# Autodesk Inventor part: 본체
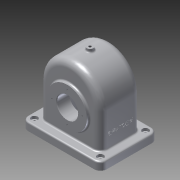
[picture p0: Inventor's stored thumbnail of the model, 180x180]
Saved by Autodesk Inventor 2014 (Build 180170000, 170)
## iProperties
Created: 2016-10
Part Number: 본체
Material: 알루미늄 6061
Document SubType Name: Modeling
Designer: a
Density: 2.71 g/cm^3
Appearance: 알루미늄 - 평지
Mass: 1261.07 g
Surface Area: 1205.98 cm^2
Volume: 465.341 cm^3
Author: a
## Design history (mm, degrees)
sketch "스케치1"
  geometry: L1 (110, 15)-(0, 15); L2 (0, 15)-(0, 0); L3 (0, 0)-(110, 0); L4 (110, 0)-(110, 15)
  constraints: 8 end point, 2 parallel, 1 horizontal, 1 perpendicular
  dimensions: "d0" = 15 distance of L1.end L2.end; "d1" = 110 distance of L1.start L1.end
extrude "돌출1" new body sketch "스케치1" distance "d2" = 150; taper "d3" = 0 deg
node "작업 평면1"
sketch "스케치2"
  geometry: L1 (0, 0)-(-150, 0) reference; L2 (-150, 0)-(-150, 15) reference; L3 (-150, 15)-(0, 15) reference; L4 (0, 15)-(0, 0) reference; L5 (-133, 15)-(-133, 138); L6 (-133, 138)-(-17, 138); L7 (-17, 138)-(-17, 15); 2 further points
  constraints: 6 end point, 2 midpoint, 2 perpendicular, 2 point on line, 1 parallel, 1 vertical alignment
  dimensions: "d4" = 116 distance of L5.end L6.end; "d20" = 123 distance of L5.start L5.end
extrude "돌출2" join sketch "스케치2" stored distance "d5" = 77; taper "d6" = 0 deg
fillet "모깎기1" dims "d7" = 58
sketch "스케치3"
  geometry: L1 (0, 0)-(-150, 0) reference; C1 r 31 at (-75, 65)
  constraints: 1 centre point
  dimensions: "d8" = 62 diameter of C1; "d21" = 65 distance from line of L1 C1.centre
extrude "돌출3" join sketch "스케치3" distance "d10" = 10; taper "d11" = 0 deg
node "작업 평면2"
sketch "스케치4"
  geometry: L1 (0, 0)-(-150, 0) reference; L2 (-150, 0)-(-150, 15) reference; L3 (-150, 15)-(-133, 15) reference; L4 (-133, 15)-(-133, 80) reference; L5 (-17, 80)-(-17, 15) reference; L6 (-17, 15)-(0, 15) reference; L7 (0, 15)-(0, 0) reference; L8 (-127, 80)-(-127, 0); L9 (-23, 80)-(-23, 0); A1 r 58 centre (-75, 80) between (-17, 80) and (-133, 80) reference; A2 r 52 centre (-75, 80) between (-23, 80) and (-127, 80)
  constraints: 4 end point, 2 perpendicular, 2 point on circle, 2 point on line, 2 tangent, 1 centre point, 1 coincident
  dimensions: "d12" = 104 diameter of A2
extrude "돌출4" cut sketch "스케치4" stored distance "d13" = 67; taper "d14" = 0 deg
sketch "스케치5"
  geometry: L1 (0, 0)-(0, 123) reference; L2 (0, 123)-(77, 123) reference; L3 (77, 123)-(77, 81) reference; L4 (77, 81)-(87, 81) reference; L5 (87, 81)-(87, 19) reference; L6 (87, 19)-(77, 19) reference; L7 (77, 19)-(77, 0) reference; L8 (77, 0)-(93.5, 0) reference; L9 (93.5, 0)-(93.5, -15) reference; L10 (93.5, -15)-(72, -15) reference; L11 (72, -15)-(72, 117) reference; L12 (72, 117)-(5, 117) reference; L13 (5, 117)-(5, -15) reference; L14 (5, -15)-(-16.5, -15) reference; L15 (-16.5, -15)-(-16.5, 0) reference; L16 (-16.5, 0)-(0, 0) reference; L17 (5, 89.747)-(19, 78); L18 (19, 78)-(19, 22); L19 (19, 22)-(5, 10.253); L20 (0, 87.5)-(-5, 87.5); L21 (-5, 87.5)-(-5, 12.5); L22 (-5, 12.5)-(0, 12.5); L23 (-5, 50)-(19, 50); L24 (5, 89.747)-(0, 93.943); 1 further point
  constraints: 16 end point, 5 point on line, 4 perpendicular, 3 midpoint, 2 horizontal alignment, 1 collinear, 1 equal length, 1 parallel
  dimensions: "d15" = 56 distance of L17.end L18.end; "d16" = 50 deg angle of L18 L17; "d17" = 75 distance of L20.end L21.end; "d18" = 5 distance of L20.start L20.end; "d79" = 24 distance between parallel lines of L18 L21
revolve "회전1" sketch "스케치5" stored, may be unused: angle "d19" = 90 deg
fillet "모깎기2" dims "d22" = 13
fillet "모깎기3" dims "d23" = 8
fillet "모깎기4" dims "d24" = 12
sketch "스케치6"
  geometry: C1 r 37.5 at (0, 0) reference; C2 r 20 at (0, 0); 1 further point
  constraints: 1 centre point, 1 coincident
  dimensions: "d25" = 40 diameter of C2
extrude "돌출5" cut sketch "스케치6" stored distance "d26" = 67; taper "d27" = 0 deg
chamfer "모따기1" distance "d28" = 1; stored, may be unused: second distance "d29" = 2, angle "d30" = 45 deg
fillet "모깎기5" dims "d31" = 3
sketch "스케치7"
  geometry: C1 r 37.5 at (0, 0) reference; 2 further points
  dimensions: "d32" = 29 distance of point (0, 29) C1.centre
hole "구멍1" sketch "스케치7" at (0, 29) diameter "d33" = 2.459; stored, may be unused: countersink angle "d37" = 90 deg, drill point angle "d39" = 118 deg; dims "d34" = 6, "d35" = 4, "d36" = 2, "d38" = 8
node "작업축1"
sketch "스케치8"
  geometry: C1 r 31 at (0, 0) reference; 2 further points
  dimensions: "d43" = 26 distance of point (0, 26) C1.centre
hole "구멍2" sketch "스케치8" at (0, 26) diameter "d44" = 2.459; stored, may be unused: countersink angle "d48" = 90 deg, drill point angle "d50" = 118 deg; dims "d45" = 6, "d46" = 4, "d47" = 2, "d49" = 8
node "작업 평면4"
  node "작업 평면3"
sketch "스케치9"
  geometry: C1 r 6 at (0, 0); 1 further point
  constraints: 1 centre point
  dimensions: "d55" = 12 diameter of C1
extrude "돌출6" join sketch "스케치9" stored distance "d56" = 67; taper "d57" = 0 deg
fillet "모깎기6" dims "d58" = 3
sketch "스케치10"
  geometry: C1 r 6 at (0, 0) reference; 1 further point
hole "구멍3" sketch "스케치10" at (0, 0) diameter "d59" = 4.459; stored, may be unused: countersink angle "d63" = 90 deg, drill point angle "d65" = 118 deg; dims "d60" = 20, "d61" = 4, "d62" = 2, "d64" = 20
fillet "모깎기7" dims "d66" = 3
sketch "스케치11"
  geometry: L1 (-17.5, -80)-(68.5, -80) reference; L2 (-13, 0)-(-13, -62) reference; 2 further points
  constraints: 1 other
  dimensions: "d67" = 40 distance from line of L1 point (25.5, -40); "d68" = 38.5 distance from line of point (25.5, -40) L2
feature "엠보싱1" sketch "스케치11" dims "d0" = 15, "d1" = 110, "d69" = 0.5, "d70" = 0
sketch "스케치12"
  geometry: A1 r 9 centre (86, -135) between (86, -144) and (95, -135) reference; A2 r 9 centre (86, -9) between (95, -9) and (86, 0) reference; A3 r 9 centre (0, -9) between (0, 0) and (-9, -9) reference; A4 r 9 centre (0, -135) between (-9, -135) and (0, -144) reference; 1 further point
hole "구멍4" sketch "스케치12" at (0, -9), (86, -9), (86, -135), (0, -135) diameter "d71" = 5; stored, may be unused: countersink angle "d75" = 90 deg, drill point angle "d77" = 118 deg; dims "d72" = 20, "d73" = 12, "d74" = 5, "d76" = 20
fillet "모깎기8" dims "d78" = 3
node "솔리드1"
pattern_circular "원형 패턴1" dims angle "d41" = 360 deg
pattern_circular "원형 패턴2" dims angle "d52" = 360 deg
node "절단 모서리 투영1"
node "절단 모서리 투영2"
node "절단 모서리 투영3"
other parameters: "d54" = 6
